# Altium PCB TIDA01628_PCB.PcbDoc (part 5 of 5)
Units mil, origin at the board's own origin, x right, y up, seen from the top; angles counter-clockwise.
Board outline 14212.6 x 5944.88 mil, 4 copper layers (Top Layer, GND, 5V, Bottom Layer), stack 60.8 mil thick; 304 components, 201 nets, 839 pads, 2143 vias.
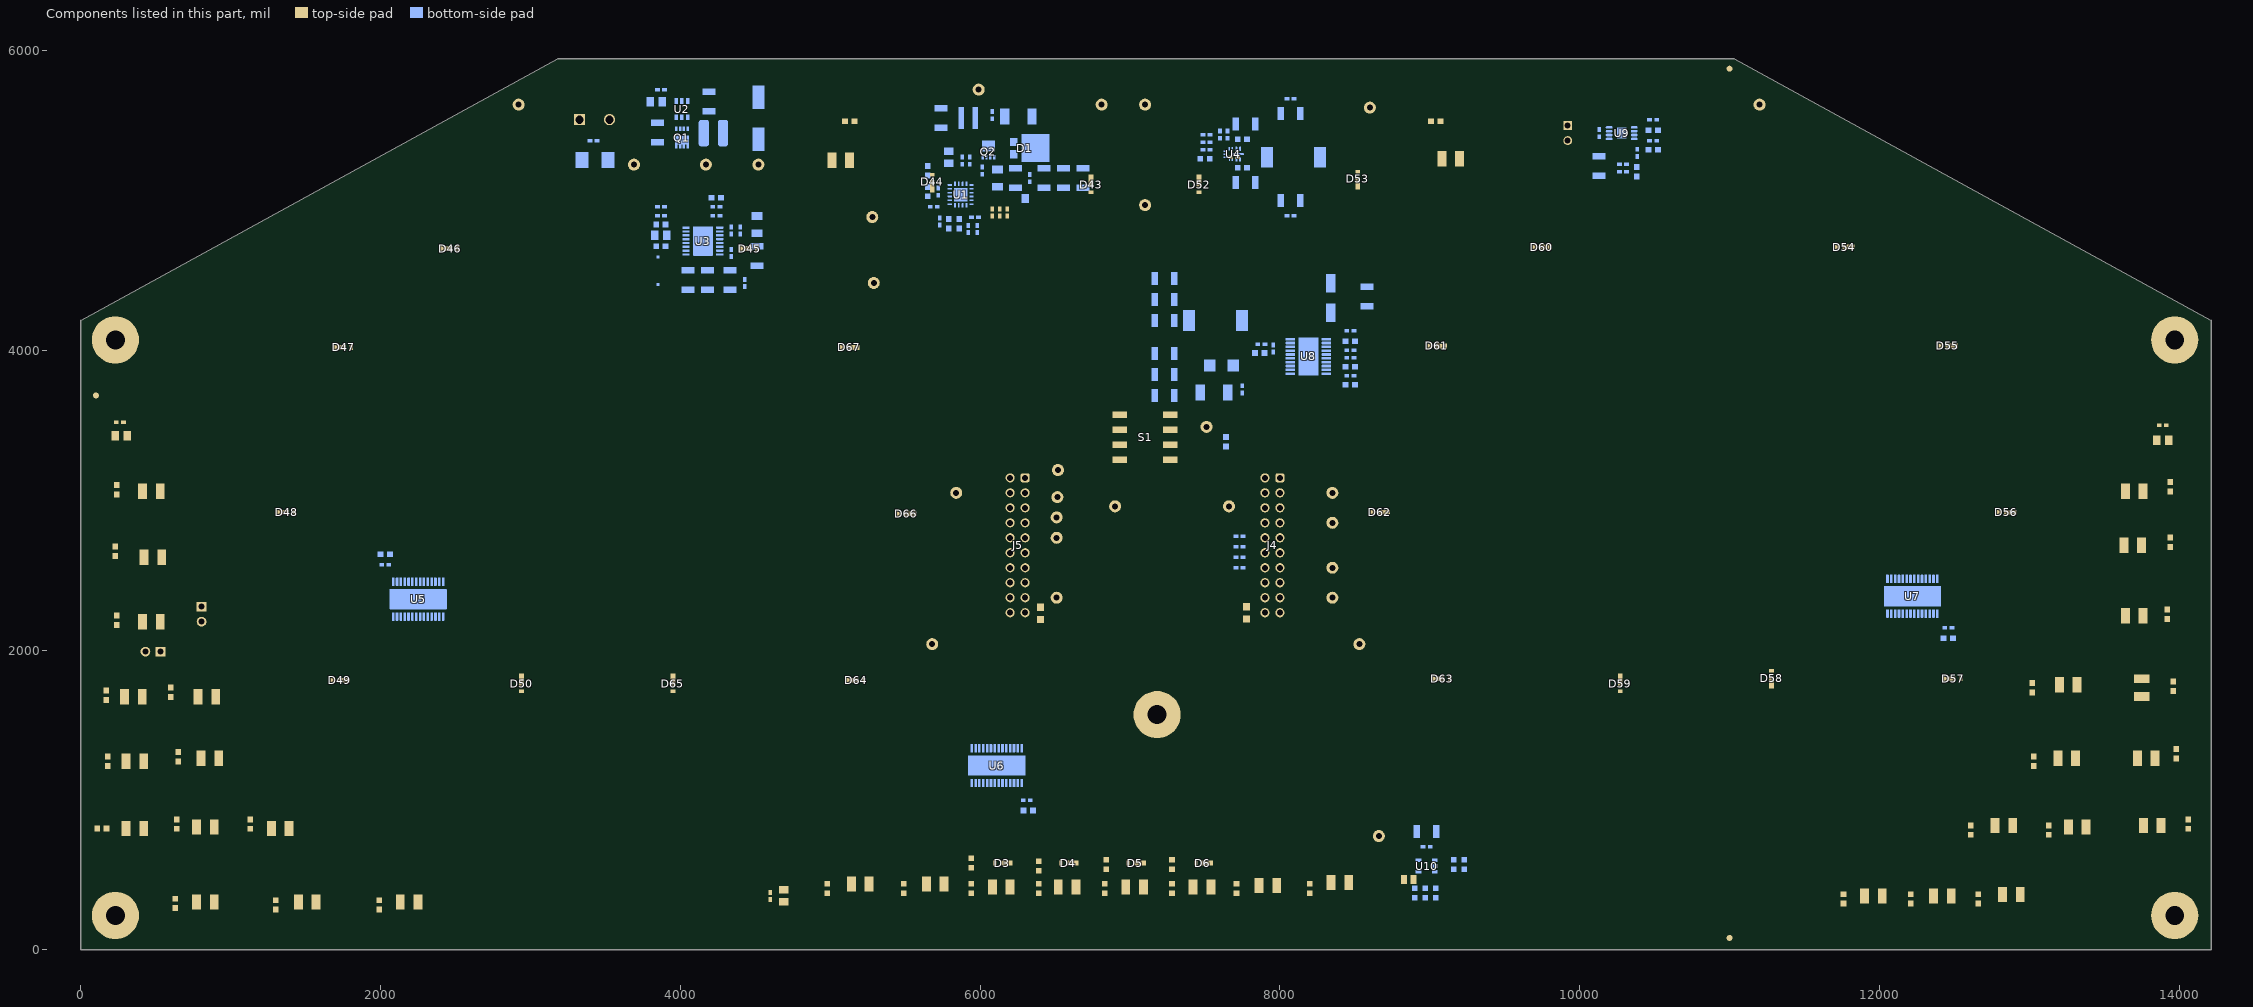
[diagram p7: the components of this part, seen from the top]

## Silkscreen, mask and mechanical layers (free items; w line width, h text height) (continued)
Drill Drawing:
  circle w10: c718.62,11178.83 r33.33
  lines w10: 685.29,10412.17 701.96,10412.17 701.96,10395.5 735.29,10395.5 735.29,10412.17 751.96,10412.17 751.96,10445.5 735.29,10445.5 735.29,10462.17 701.96,10462.17 701.96,10445.5 685.29,10445.5 685.29,10412.17 ; 685.29,10562.17 701.96,10562.17 718.62,10545.5 735.29,10562.17 751.96,10562.17 735.29,10578.83 751.96,10595.5 735.29,10595.5 718.62,10612.17 701.96,10595.5 685.29,10595.5 701.96,10578.83 685.29,10562.17 ; 685.29,10695.5 751.96,10695.5 751.96,10762.17 685.29,10762.17 685.29,10695.5 ; 685.29,10845.5 718.62,10862.17 751.96,10845.5 735.29,10878.83 751.96,10912.17 718.62,10895.5 685.29,10912.17 701.96,10878.83 685.29,10845.5 ; 685.29,11062.17 751.96,11062.17 718.62,10995.5 685.29,11062.17
  lines w15: 625.5,10350.5 11276.54,10350.5 ; 625.5,11250.5 11276.54,11250.5 ; 1176.38,10200.5 1176.38,11400.5 ; 1836.2,10200.5 1836.2,11400.5 ; 2985.86,10200.5 2985.86,11400.5 ; 3491.74,10200.5 3491.74,11400.5 ; 4225.54,10200.5 4225.54,11400.5 ; 5725.09,10200.5 5725.09,11400.5 ; 6314.94,10200.5 6314.94,11400.5 ; 7060.74,10200.5 7060.74,11400.5 ; 7710.57,10200.5 7710.57,11400.5 ; 8564.33,10200.5 8564.33,11400.5 ; 9897.94,10200.5 9897.94,11400.5 ; 625.5,10200.5 11276.54,10200.5 11276.54,11400.5 625.5,11400.5 625.5,10200.5
  text "Symbol" at 715.5,11295.5 h72
  text "Count" at 1221.38,11295.5 h72
  text "Hole Size" at 1881.2,11295.5 h72
  text "Plated" at 3030.86,11295.5 h72
  text "Hole Type" at 3536.74,11295.5 h72
  text "Drill Layer Pair" at 4270.54,11295.5 h72
  text "Via/Pad" at 5770.09,11295.5 h72
  text "Pad Shape" at 6359.94,11295.5 h72
  text "Template" at 7105.74,11295.5 h72
  text "Description" at 7755.57,11295.5 h72
  text "Hole Tolerance (+)" at 8609.33,11295.5 h72
  text "Hole Tolerance (-)" at 9942.94,11295.5 h72
  text "2" at 1221.38,11145.5 h60
  text "40.16mil (1.020mm)" at 1881.2,11145.5 h60
  text "PTH" at 3030.86,11145.5 h60
  text "Round" at 3536.74,11145.5 h60
  text "Top Layer - Bottom Layer" at 4270.54,11145.5 h60
  text "Pad" at 5770.09,11145.5 h60
  text "(Mixed)" at 6359.94,11145.5 h60
  text "(Mixed)" at 7105.74,11145.5 h60
  text "2" at 1221.38,10995.5 h60
  text "55.12mil (1.400mm)" at 1881.2,10995.5 h60
  text "PTH" at 3030.86,10995.5 h60
  text "Round" at 3536.74,10995.5 h60
  text "Top Layer - Bottom Layer" at 4270.54,10995.5 h60
  text "Pad" at 5770.09,10995.5 h60
  text "(Mixed)" at 6359.94,10995.5 h60
  text "(Mixed)" at 7105.74,10995.5 h60
  text "5" at 1221.38,10845.5 h60
  text "125.98mil (3.200mm)" at 1881.2,10845.5 h60
  text "PTH" at 3030.86,10845.5 h60
  text "Round" at 3536.74,10845.5 h60
  text "Top Layer - Bottom Layer" at 4270.54,10845.5 h60
  text "Pad" at 5770.09,10845.5 h60
  text "Rounded" at 6359.94,10845.5 h60
  text "c800h320" at 7105.74,10845.5 h60
  text "72" at 1221.38,10695.5 h60
  text "40.00mil (1.016mm)" at 1881.2,10695.5 h60
  text "PTH" at 3030.86,10695.5 h60
  text "Round" at 3536.74,10695.5 h60
  text "Top Layer - Bottom Layer" at 4270.54,10695.5 h60
  text "Pad" at 5770.09,10695.5 h60
  text "(Mixed)" at 6359.94,10695.5 h60
  text "(Mixed)" at 7105.74,10695.5 h60
  text "108" at 1221.38,10545.5 h60
  text "7.87mil (0.200mm)" at 1881.2,10545.5 h60
  text "PTH" at 3030.86,10545.5 h60
  text "Round" at 3536.74,10545.5 h60
  text "Top Layer - Bottom Layer" at 4270.54,10545.5 h60
  text "Via" at 5770.09,10545.5 h60
  text "Rounded" at 6359.94,10545.5 h60
  text "(Mixed)" at 7105.74,10545.5 h60
  text "2035" at 1221.38,10395.5 h60
  text "10.00mil (0.254mm)" at 1881.2,10395.5 h60
  text "PTH" at 3030.86,10395.5 h60
  text "Round" at 3536.74,10395.5 h60
  text "Top Layer - Bottom Layer" at 4270.54,10395.5 h60
  text "Via" at 5770.09,10395.5 h60
  text "Rounded" at 6359.94,10395.5 h60
  text "(Mixed)" at 7105.74,10395.5 h60
  text "2224 Total" at 1221.38,10245.5 h60
  text ".Layer_Name" at 577,-858.49 h60
M17 Embedded Cavity:
  text ".Layer_Name" at 577,-858.49 h60
M18 Embedded Assembly:
  text ".Layer_Name" at 577,-858.49 h60
M19 Embedded Keepout:
  text ".Layer_Name" at 567,-858.49 h60

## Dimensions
0,-400 to 1000,-400 on M2 Board Dimensions
0,0 to 14212.6,10 on M2 Board Dimensions
0,0 to 11032.68,5944.88 on M2 Board Dimensions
